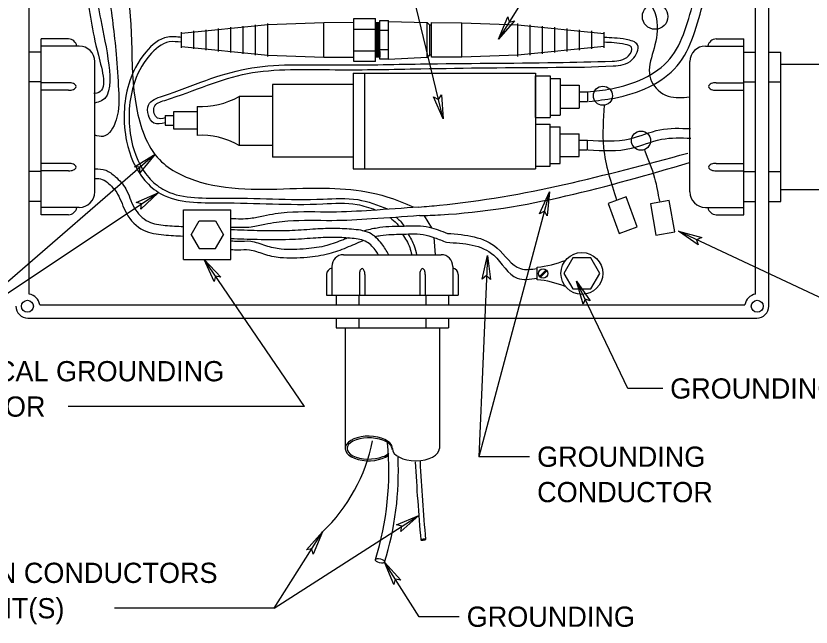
# Model space of a CAD drawing. Extents: x 99981 to 128681, y 99783 to 102182.
# Drawn here: x 126688.5 to 127160.6, y 100530.7 to 100893.4 of the extents above; entities that cross this region are included whole.
import ezdxf

# ---------------------------------------------------------------- set-up
doc = ezdxf.new("R2010")
doc.units = 0
doc.layers.add('Level 1', color=7, linetype='Continuous')

msp = doc.modelspace()

# ---------------------------------------------------------------- linework, layer by layer
at = {"layer": 'Level 1'}
for p, q in [((127132.95, 101132.19), (126975.04, 100879.69)), ((126942.15, 100832.29), (126890.59, 101046.26)), ((127135.49, 100721.17), (127135.49, 101001.42)), ((126696.31, 100728.23), (126696.31, 100994.36)), ((127127.69, 100728.23), (127127.69, 100994.36)), ((126871.3, 100889.36), (126838.02, 100888.11)), ((126838.02, 100869.41), (126838.02, 100888.87)), ((126889.22, 100889.39), (126871.3, 100889.36)), ((126871.3, 100868.88), (126871.3, 100889.36)), ((126889.22, 100866.34), (126889.22, 100891.95)), ((126889.22, 100891.95), (126902.03, 100891.95)), ((126902.03, 100866.34), (126902.03, 100891.95)), ((126902.03, 100889.41), (126904.59, 100889.41)), ((126902.03, 100889.41), (126902.67, 100868.93)), ((126902.67, 100889.41), (126903.31, 100868.93)), ((126903.31, 100889.41), (126903.95, 100868.93)), ((126903.95, 100889.41), (126904.59, 100868.93)), ((126904.59, 100867.65), (126904.59, 100890.69)), ((126904.59, 100890.69), (126909.71, 100890.69)), ((126909.71, 100867.65), (126909.71, 100890.69)), ((126909.71, 100890.05), (126932.75, 100889.39)), ((126932.75, 100868.9), (126932.75, 100889.39)), ((126934.01, 100888.13), (126932.75, 100889.39)), ((126935.31, 100868.9), (126935.31, 100889.39)), ((126935.31, 100889.39), (126953.23, 100889.36)), ((126953.23, 100868.88), (126953.23, 100889.36)), ((126953.23, 100889.36), (126986.52, 100888.11)), ((126986.52, 100869.41), (126986.52, 100888.87)), ((126838.02, 100888.11), (126786.81, 100882.99)), ((126794.1, 100873.79), (126794.1, 100884.47)), ((126801.43, 100873.08), (126801.43, 100885.21)), ((126808.75, 100872.33), (126808.75, 100885.95)), ((126816.05, 100871.62), (126816.05, 100886.67)), ((126823.37, 100870.87), (126823.37, 100887.41)), ((126830.69, 100870.16), (126830.69, 100888.13)), ((126889.22, 100885.55), (126902.03, 100885.55)), ((126904.59, 100884.93), (126909.71, 100884.93)), ((126934.01, 100888.13), (126935.31, 100888.13)), ((126934.01, 100888.13), (126934.03, 100870.18)), ((126986.52, 100888.11), (127037.73, 100882.99)), ((126993.84, 100870.16), (126993.84, 100888.13)), ((127001.17, 100870.87), (127001.17, 100887.41)), ((127008.49, 100871.62), (127008.49, 100886.67)), ((127015.79, 100872.33), (127015.79, 100885.95)), ((127023.11, 100873.08), (127023.11, 100885.21)), ((127030.43, 100873.79), (127030.43, 100884.47)), ((126703.41, 100775.45), (126703.41, 100879.75)), ((126719.72, 100879.75), (126703.41, 100879.75)), ((126786.81, 100874.54), (126786.81, 100883.75)), ((127037.73, 100874.54), (127037.73, 100883.75)), ((127104.27, 100879.75), (127120.59, 100879.75)), ((127120.59, 100775.45), (127120.59, 100879.75)), ((126726.11, 100875.49), (126703.41, 100875.49)), ((126786.81, 100875.3), (126838.02, 100870.18)), ((127037.73, 100875.3), (126986.52, 100870.18)), ((127097.89, 100875.49), (127120.59, 100875.49)), ((126703.41, 100871.94), (126696.31, 100871.94)), ((126838.02, 100870.18), (126871.3, 100868.88)), ((126889.22, 100872.74), (126902.03, 100872.74)), ((126904.59, 100873.41), (126909.71, 100873.41)), ((126932.75, 100868.9), (126934.03, 100870.18)), ((126935.31, 100870.18), (126934.03, 100870.18)), ((126986.52, 100870.18), (126953.23, 100868.88)), ((127120.59, 100871.94), (127127.69, 100871.94)), ((127135.49, 100871.94), (127142.58, 100871.94)), ((127142.58, 100783.25), (127142.58, 100871.94)), ((126735.33, 100788.93), (126735.33, 100866.27)), ((126871.3, 100868.88), (126889.22, 100868.9)), ((126902.03, 100866.34), (126889.22, 100866.34)), ((126904.59, 100868.93), (126902.03, 100868.93)), ((126909.71, 100867.65), (126904.59, 100867.65)), ((126909.71, 100867.65), (126932.75, 100868.9)), ((126953.23, 100868.88), (126935.31, 100868.9)), ((127088.66, 100788.93), (127088.66, 100866.27)), ((127142.58, 100864.85), (127238.09, 100864.85)), ((126888.78, 100859.47), (126996.96, 100859.47)), ((126888.78, 100859.47), (126888.78, 100802.71)), ((126895.38, 100859.47), (126895.38, 100802.71)), ((126996.96, 100859.47), (126996.96, 100802.71)), ((126997.06, 100857.89), (127005.66, 100857.89)), ((126997.06, 100833.04), (126997.06, 100857.89)), ((127005.66, 100857.89), (127005.66, 100833.04)), ((127005.66, 100856.33), (127011.68, 100856.33)), ((127011.68, 100856.33), (127011.68, 100834.59)), ((126703.41, 100854.2), (126696.31, 100854.2)), ((126719.82, 100853.64), (126703.41, 100853.64)), ((126888.78, 100852.69), (126840.87, 100852.69)), ((126840.87, 100852.69), (126840.87, 100809.5)), ((126888.78, 100852.69), (126888.78, 100809.5)), ((127011.68, 100852.26), (127022.95, 100852.26)), ((127022.95, 100852.26), (127022.95, 100838.68)), ((127104.17, 100853.64), (127120.59, 100853.64)), ((127120.59, 100854.2), (127127.69, 100854.2)), ((127135.49, 100854.2), (127142.58, 100854.2)), ((126719.82, 100849.38), (126703.41, 100849.38)), ((127022.95, 100848.33), (127027.96, 100848.33)), ((127027.96, 100848.33), (127027.96, 100842.6)), ((127104.17, 100849.38), (127120.59, 100849.38)), ((126821, 100845.6), (126821, 100816.59)), ((126840.87, 100845.6), (126821, 100845.6)), ((127022.95, 100842.6), (127027.96, 100842.6)), ((126796.17, 100839.65), (126796.17, 100822.53)), ((127011.68, 100838.68), (127022.95, 100838.68)), ((126777.03, 100834.31), (126782.04, 100834.31)), ((126777.03, 100834.31), (126777.03, 100828.58)), ((126997.06, 100833.04), (127005.66, 100833.04)), ((127005.66, 100834.59), (127011.68, 100834.59)), ((126777.03, 100828.58), (126782.04, 100828.58)), ((126997.06, 100829.14), (127005.66, 100829.14)), ((126997.06, 100829.14), (126997.06, 100804.29)), ((127005.66, 100804.29), (127005.66, 100829.14)), ((127005.66, 100827.58), (127011.68, 100827.58)), ((127011.68, 100805.84), (127011.68, 100827.58)), ((127011.68, 100823.51), (127022.95, 100823.51)), ((127022.95, 100809.93), (127022.95, 100823.51)), ((127022.95, 100819.58), (127027.96, 100819.58)), ((127027.96, 100813.85), (127027.96, 100819.58)), ((126840.87, 100816.59), (126821, 100816.59)), ((127022.95, 100813.85), (127027.96, 100813.85)), ((126771.12, 100811.34), (126650.92, 100707.2)), ((126888.78, 100809.5), (126840.87, 100809.5)), ((127011.68, 100809.93), (127022.95, 100809.93)), ((126719.82, 100805.82), (126703.41, 100805.82)), ((126997.06, 100804.29), (127005.66, 100804.29)), ((127005.66, 100805.84), (127011.68, 100805.84)), ((127104.17, 100805.82), (127120.59, 100805.82)), ((126703.41, 100800.99), (126696.31, 100800.99)), ((126719.82, 100801.56), (126703.41, 100801.56)), ((126888.78, 100802.71), (126996.96, 100802.71)), ((127104.17, 100801.56), (127120.59, 100801.56)), ((127120.59, 100800.99), (127127.69, 100800.99)), ((127135.49, 100800.99), (127142.58, 100800.99)), ((127142.58, 100790.35), (127238.09, 100790.35)), ((126650.92, 100707.2), (126773.02, 100788.5)), ((127005.33, 100789.01), (126963.35, 100631.85)), ((126703.41, 100783.25), (126696.31, 100783.25)), ((127120.59, 100783.25), (127127.69, 100783.25)), ((127135.49, 100783.25), (127142.58, 100783.25)), ((126726.11, 100779.71), (126703.41, 100779.71)), ((126788.05, 100778.38), (126816.2, 100778.38)), ((126788.05, 100748.78), (126788.05, 100778.38)), ((126816.2, 100748.78), (126816.2, 100778.38)), ((127097.89, 100779.71), (127120.59, 100779.71)), ((126719.72, 100775.45), (126703.41, 100775.45)), ((126792.56, 100763.58), (126797.34, 100771.87)), ((126797.34, 100771.87), (126806.91, 100771.87)), ((126806.91, 100771.87), (126811.69, 100763.58)), ((126930.99, 100774.86), (126935.16, 100767.63)), ((127104.27, 100775.45), (127120.59, 100775.45)), ((126792.56, 100763.58), (126797.34, 100755.3)), ((126806.91, 100755.3), (126811.69, 100763.58)), ((126936.7, 100761.84), (126937.37, 100751.64)), ((127193.96, 100712.95), (127081.91, 100765.67)), ((126797.34, 100755.3), (126806.91, 100755.3)), ((126788.05, 100748.78), (126816.2, 100748.78)), ((126859.87, 100661.58), (126800.29, 100748.76)), ((126882.99, 100751.68), (126940.99, 100751.68)), ((126968.4, 100751.21), (126963.35, 100631.85)), ((126876.08, 100744.76), (126876.08, 100727.73)), ((126947.91, 100744.76), (126947.91, 100727.73)), ((126997.9, 100736.85), (126997.9, 100744.25)), ((127003.28, 100742.71), (126999.36, 100738.79)), ((126872.88, 100739.97), (126872.88, 100727.73)), ((126892.46, 100740.04), (126892.46, 100727.73)), ((126895.66, 100740.04), (126895.66, 100727.73)), ((126928.33, 100740.04), (126928.33, 100727.73)), ((126931.52, 100740.04), (126931.52, 100727.73)), ((126951.11, 100739.97), (126951.11, 100727.73)), ((127003.78, 100742.21), (126999.86, 100738.3)), ((127051.81, 100672.33), (127021.28, 100736.07)), ((126872.88, 100727.73), (126951.11, 100727.73)), ((126878.74, 100727.73), (126878.74, 100722.41)), ((126892.04, 100727.73), (126892.04, 100722.41)), ((126931.95, 100727.73), (126931.95, 100722.41)), ((126945.25, 100727.73), (126945.25, 100722.41)), ((126702.66, 100721.88), (127121.34, 100721.88)), ((126695.6, 100714.07), (127128.39, 100714.07)), ((126878.74, 100713.7), (126878.74, 100708.37)), ((126892.04, 100713.7), (126892.04, 100708.37)), ((126931.95, 100713.7), (126931.95, 100708.37)), ((126945.25, 100713.7), (126945.25, 100708.37)), ((126878.74, 100708.37), (126945.25, 100708.37)), ((126884.05, 100708.37), (126884.05, 100636.74)), ((126939.93, 100708.37), (126939.93, 100636.74)), ((127072.49, 100672.33), (127051.81, 100672.33)), ((126859.87, 100661.58), (126719.48, 100661.58)), ((126993.5, 100631.85), (126963.35, 100631.85)), ((126841.83, 100541.93), (126927.67, 100597.04)), ((126841.83, 100541.93), (126870.52, 100587.24)), ((126927.86, 100536.91), (126907.39, 100569.2)), ((126841.83, 100541.93), (126747.08, 100541.93)), ((126951.7, 100536.91), (126927.86, 100536.91))]:
    msp.add_line(p, q, dxfattribs=at)
for points in [[(126984.55, 100890.38), (126975.04, 100879.69), (126980.49, 100892.91), (126981.34, 100889.77)], [(126941.17, 100846.56), (126942.15, 100832.29), (126936.52, 100845.43), (126939.36, 100843.84)], [(126782, 100826.38), (126796.25, 100826.38), (126796.25, 100836.49), (126782, 100836.49)], [(126758.89, 100803.92), (126771.12, 100811.34), (126762.03, 100800.3), (126762.14, 100803.56)], [(126759.95, 100782.67), (126773.02, 100788.5), (126762.61, 100778.69), (126763.12, 100781.91)], [(126999.38, 100776), (127005.33, 100789.01), (127004, 100774.76), (127002.26, 100777.52)], [(127040.12, 100782.08), (127046.59, 100764.3), (127057.26, 100768.18), (127050.79, 100785.96)], [(127065.25, 100781.96), (127068.53, 100763.32), (127079.71, 100765.3), (127076.43, 100783.93)], [(127093.65, 100757.5), (127081.91, 100765.67), (127095.69, 100761.83), (127092.67, 100760.61)], [(126806.27, 100735.77), (126800.29, 100748.76), (126810.22, 100738.47), (126807, 100738.95)], [(126965.41, 100737.22), (126968.4, 100751.21), (126970.19, 100737.02), (126967.9, 100739.34)], [(127035.15, 100740.59), (127029.83, 100749.8), (127019.19, 100749.8), (127013.86, 100740.59), (127019.19, 100731.38), (127029.83, 100731.38)], [(127025.21, 100722.32), (127021.28, 100736.07), (127029.53, 100724.38), (127026.41, 100725.35)], [(126914.51, 100591.44), (126927.67, 100597.04), (126917.1, 100587.41), (126917.67, 100590.62)], [(126860.95, 100576.6), (126870.52, 100587.24), (126865, 100574.04), (126864.16, 100577.19)], [(126912.92, 100556.01), (126907.39, 100569.2), (126916.96, 100558.57), (126913.75, 100559.16)]]:
    msp.add_lwpolyline(points, close=True, dxfattribs=at)
for centre, radius in [((127068, 100893.02), 7.57), ((127037.02, 100846.03), 5.68), ((127059.62, 100819.39), 5.68), ((127024.51, 100740.59), 12.42), ((127001.52, 100740.55), 2.77), ((126695.34, 100721.09), 3.55), ((127128.66, 100721.09), 3.55)]:
    msp.add_circle(centre, radius, dxfattribs=at)
for centre, radius, start, end in [((126719.72, 100874.78), 4.97, 8.2132, 90), ((127104.27, 100874.78), 4.97, 90, 171.7868), ((126726.11, 100866.26), 9.22, 0, 90), ((127097.89, 100866.26), 9.22, 90, 180), ((126720.35, 100847.3), 6.36, 68.7228, 94.7765), ((126721.57, 100850.42), 3.01, 21.2222, 68.7778), ((126721.57, 100852.6), 3.01, 291.2222, 338.7778), ((127102.43, 100850.42), 3.01, 111.2222, 158.7778), ((127102.43, 100852.6), 3.01, 201.2222, 248.7778), ((127103.64, 100847.3), 6.36, 85.2235, 111.2772), ((126720.35, 100855.72), 6.36, 265.2235, 291.2772), ((127103.64, 100855.72), 6.36, 248.7228, 274.7765), ((126720.35, 100799.48), 6.36, 68.7228, 94.7765), ((126721.57, 100802.6), 3.01, 21.2222, 68.7778), ((127102.43, 100802.6), 3.01, 111.2222, 158.7778), ((127103.64, 100799.48), 6.36, 85.2235, 111.2772), ((126720.35, 100807.9), 6.36, 265.2235, 291.2772), ((126721.57, 100804.78), 3.01, 291.2222, 338.7778), ((127102.43, 100804.78), 3.01, 201.2222, 248.7778), ((127103.64, 100807.9), 6.36, 248.7228, 274.7765), ((126726.11, 100788.93), 9.22, 270, 360), ((127097.89, 100788.93), 9.22, 180, 270), ((126719.72, 100780.41), 4.97, 270, 351.7868), ((127104.27, 100780.41), 4.97, 188.2132, 270), ((126883, 100744.76), 6.92, 90, 180), ((126941, 100744.76), 6.92, 0, 90), ((126992.22, 100805.33), 61.27, 275.325, 291.5255), ((126876.61, 100739.97), 3.72, 98.2132, 180), ((126894.88, 100741.36), 2.26, 111.2222, 158.7778), ((126893.25, 100741.36), 2.26, 21.2222, 68.7778), ((126930.75, 100741.36), 2.26, 111.2222, 158.7778), ((126929.11, 100741.36), 2.26, 21.2222, 68.7778), ((126947.38, 100739.97), 3.72, 0, 81.7868), ((126897.22, 100740.44), 4.77, 158.7228, 184.7765), ((126890.91, 100740.44), 4.77, 355.2235, 21.2772), ((126933.09, 100740.44), 4.77, 158.7228, 184.7765), ((126926.77, 100740.44), 4.77, 355.2235, 21.2772), ((126992.22, 100675.85), 61.27, 68.4745, 84.675), ((126695.6, 100721.17), 7.09, 6.0467, 84.2608), ((127128.4, 100721.17), 7.09, 95.7392, 174.2608), ((126695.6, 100721.17), 7.09, 180, 270), ((127128.4, 100721.17), 7.09, 270, 360), ((126800.18, 100661.15), 102.03, 313.5776, 348.7697), ((126734.62, 100623.02), 175.28, 342.6714, 5.5575), ((126904.17, 100633.3), 8.55, 23.762, 75.0443), ((126904.07, 100640.29), 8.69, 285.02, 312.8704), ((126904.07, 100640.29), 8.69, 335.5297, 335.8989), ((126734.62, 100623.02), 180.96, 342.6983, 2.7267), ((128246.93, 100699.98), 1323.26, 183.08264, 185.09483), ((128246.93, 100699.98), 1320.42, 183.08264, 185.09483)]:
    msp.add_arc(centre, radius, start, end, dxfattribs=at)
for centre, major_axis, ratio, start_param, end_param in [((126798.65, 100940.97), (0, -101.39), 0.64994, 6.245521, 6.629239), ((126798.65, 100721.21), (0, 101.39), 0.64994, 5.937131, 6.32085), ((126898.03, 100636.74), (13.97, 0), 0.524286, 6.206747, 11.96981), ((126898.03, 100636.74), (12.95, 0), 0.486783, 0.869952, 5.407175), ((126926, 100636.74), (13.97, 0), 0.524286, 3.150248, 6.285615)]:
    msp.add_ellipse(centre, major_axis=major_axis, ratio=ratio, start_param=start_param, end_param=end_param, dxfattribs=at)
for centre, major_axis, ratio in [((126930.3, 100582.59), (1.41, 0.13), 0.38426), ((126904.69, 100570.06), (2.76, -0.65), 0.436494)]:
    msp.add_ellipse(centre, major_axis=major_axis, ratio=ratio, dxfattribs=at)
for points in [[(127028.7, 100842.7), (127043.81, 100844.68), (127081.11, 100863.74), (127096.88, 100902.1), (127107.23, 100945.75), (127095.48, 100981.83), (127077.62, 100992.04), (127031.02, 100994.96), (126964.69, 100995.67), (126892.64, 100999.2), (126822.45, 100997.07), (126760.53, 100992.03), (126730.71, 100976.71), (126722.94, 100959.9), (126726.25, 100929.46), (126733.23, 100890.29), (126737.45, 100870.11), (126736.48, 100847.55), (126734.69, 100847.35)], [(127027.96, 100848.33), (127042.1, 100850.18), (127076.66, 100867.84), (127091.46, 100903.85), (127101.34, 100945.51), (127090.76, 100977.99), (127075.95, 100986.46), (127030.82, 100989.29), (126964.52, 100989.99), (126892.59, 100993.52), (126822.77, 100991.4), (126762.12, 100986.46), (126734.62, 100972.34), (126729.19, 100959.09), (126731.8, 100930.68), (126738.85, 100891.14), (126743.65, 100864.09), (126739.33, 100843.02), (126735.32, 100841.71)], [(127027.96, 100936.63), (127046.33, 100939.15), (127073.13, 100956.1), (127076.66, 100972.34), (127063.96, 100980.81), (127016.01, 100981.52), (126929.97, 100985.05), (126886.95, 100987.87), (126802.32, 100984.34), (126750.13, 100973.75), (126736.03, 100954.69), (126738.85, 100937.03), (126743.79, 100906.67), (126748.02, 100870.66), (126749.43, 100849.48), (126748.02, 100831.82), (126740.26, 100821.94), (126735.32, 100822.64)], [(126786.81, 100969.12), (126777.46, 100967.32), (126761.29, 100964.83), (126746.98, 100951.13), (126751.96, 100918.13), (126760.04, 100839.04), (126773.78, 100808.1), (126797.98, 100794.83), (126858.93, 100791.1), (126908.68, 100786.11), (126924.41, 100780.11)], [(127027.96, 100907.88), (127042.29, 100907.62), (127062, 100903.76), (127069.29, 100884.45), (127065.86, 100854.42), (127075.72, 100845.83), (127088.57, 100845.4)], [(126786.81, 100880.56), (126778.65, 100880.82), (126765.66, 100871.94), (126755.53, 100852.91), (126754.26, 100818.98), (126765.03, 100795.82), (126774.53, 100787.9), (126810.32, 100782.51), (126870.82, 100781.87), (126891.09, 100781.55), (126901.87, 100778.38)], [(126777.03, 100832.86), (126772.56, 100832.74), (126770.57, 100839.28), (126776.83, 100843.27), (126825.98, 100859.2), (126877.98, 100861.47), (126928.84, 100862.04), (127009.25, 100862.9), (127043.06, 100863.75), (127054.42, 100867.45), (127057.55, 100876.27), (127050.73, 100879.4), (127037.73, 100880.56)], [(126786.72, 100877.73), (126779.49, 100877.95), (126767.84, 100869.99), (126758.34, 100852.15), (126757.12, 100819.55), (126767.34, 100797.6), (126775.74, 100790.58), (126810.55, 100785.34), (126870.86, 100784.71), (126891.5, 100784.39), (126909.03, 100778.87)], [(126777.11, 100830.03), (126770.48, 100829.85), (126767.23, 100840.52), (126775.61, 100845.86), (126825.47, 100862.02), (126877.9, 100864.31), (126928.81, 100864.88), (127009.2, 100865.73), (127042.57, 100866.58), (127052.22, 100869.71), (127054.01, 100874.77), (127050.29, 100876.48), (127037.73, 100877.73)], [(127037.83, 100840.38), (127037.42, 100815.35), (127045.09, 100784.26)], [(127027.96, 100819.58), (127053.03, 100820.53), (127070.84, 100825.82), (127089, 100826.53)], [(127028.17, 100813.91), (127053.96, 100814.88), (127071.77, 100820.18), (127089.22, 100820.86)], [(127061.64, 100813.73), (127067.69, 100797.18), (127070.51, 100783.46)], [(126927.77, 100779.99), (126939.9, 100781.05), (127087.34, 100811.9)], [(126928.13, 100774.89), (126940.61, 100775.4), (127088.5, 100806.35)], [(126735.39, 100802.75), (126741.84, 100801.78), (126747.52, 100798.05), (126753.7, 100790.79), (126758.8, 100779.59), (126767.17, 100771.38), (126777.14, 100769.11), (126788.05, 100768.46)], [(126735.48, 100797.01), (126739.76, 100796.35), (126743.73, 100793.75), (126748.86, 100787.71), (126754.07, 100776.28), (126764.34, 100766.2), (126776.33, 100763.47), (126787.71, 100762.79)], [(126927.77, 100779.99), (126899.52, 100777.99), (126875.98, 100777), (126849.56, 100776.66), (126835.54, 100774.64), (126827.72, 100773.17), (126816.29, 100773.01)], [(126928.13, 100774.89), (126899.81, 100772.89), (126876.12, 100771.89), (126849.96, 100771.56), (126836.37, 100769.6), (126828.23, 100768.07), (126816.36, 100767.9)], [(126910.81, 100773.55), (126914.47, 100770.43), (126915.93, 100768.44)], [(126914.47, 100773.76), (126916.76, 100771.56), (126919.01, 100768.64)], [(126909.79, 100751.89), (126905.84, 100758.07), (126898.39, 100764.59), (126887.69, 100766.77), (126876.89, 100767.28), (126864.77, 100766.78), (126850.85, 100765.95), (126831.84, 100765.95), (126816.24, 100766.45)], [(126894.57, 100765.78), (126898.98, 100766.95), (126902.89, 100767.7), (126909.96, 100768.53), (126917.78, 100768.7), (126926.93, 100768.86), (126933.83, 100768.03), (126944.65, 100764.37)], [(126903.64, 100751.89), (126901.82, 100754.55), (126895.96, 100759.68), (126887.03, 100761.49), (126876.87, 100761.98), (126865.03, 100761.49), (126851.01, 100760.65), (126831.75, 100760.65), (126816.07, 100761.15)], [(126886.01, 100761.71), (126882.91, 100760.59), (126873.09, 100757.16), (126860.91, 100755.21), (126845.96, 100755.05), (126836.91, 100756.99), (126827.9, 100759.53), (126820.36, 100759.53), (126816.4, 100759.7)], [(126901.89, 100762.46), (126904.89, 100763.12), (126911.71, 100763.7), (126923.02, 100764.04), (126930.34, 100763.7), (126937.08, 100761.79), (126944.15, 100759.05)], [(126918.07, 100763.9), (126922.31, 100756), (126923.52, 100751.69)], [(126921.35, 100763.99), (126924.97, 100757.04), (126926.43, 100751.69)], [(126944.73, 100764.36), (126974.22, 100755.67), (126988.18, 100743.44), (126997.88, 100743.44)], [(126894.41, 100759.96), (126884.59, 100755.77), (126874.34, 100752.18), (126861.35, 100750.1), (126845.45, 100749.93), (126835.68, 100752.03), (126827.19, 100754.43), (126820.25, 100754.43), (126816.19, 100754.59)], [(126944.23, 100759.05), (126972.19, 100751.34), (126986.19, 100737.76), (126997.88, 100737.76)]]:
    msp.add_spline(points, degree=3, dxfattribs=at)

# ---------------------------------------------------------------- texts
for s, p in [('MECHANICAL GROUNDING', (126602.65, 100676.58)), (' GROUNDING LUG', (127072.49, 100666.33)), ('CONNECTOR ', (126602.65, 100655.58)), (' GROUNDING ', (126993.5, 100625.85)), (' CONDUCTOR', (126993.5, 100604.85)), ('NO. 12 THW OR THWN CONDUCTORS', (126515.82, 100556.93)), ('TO UNDERDECK LIGHT(S) ', (126515.82, 100535.93)), (' GROUNDING ', (126951.7, 100530.91))]:
    msp.add_text(s, height=12, dxfattribs=at).set_placement(p)

doc.saveas('drawing.dxf')
